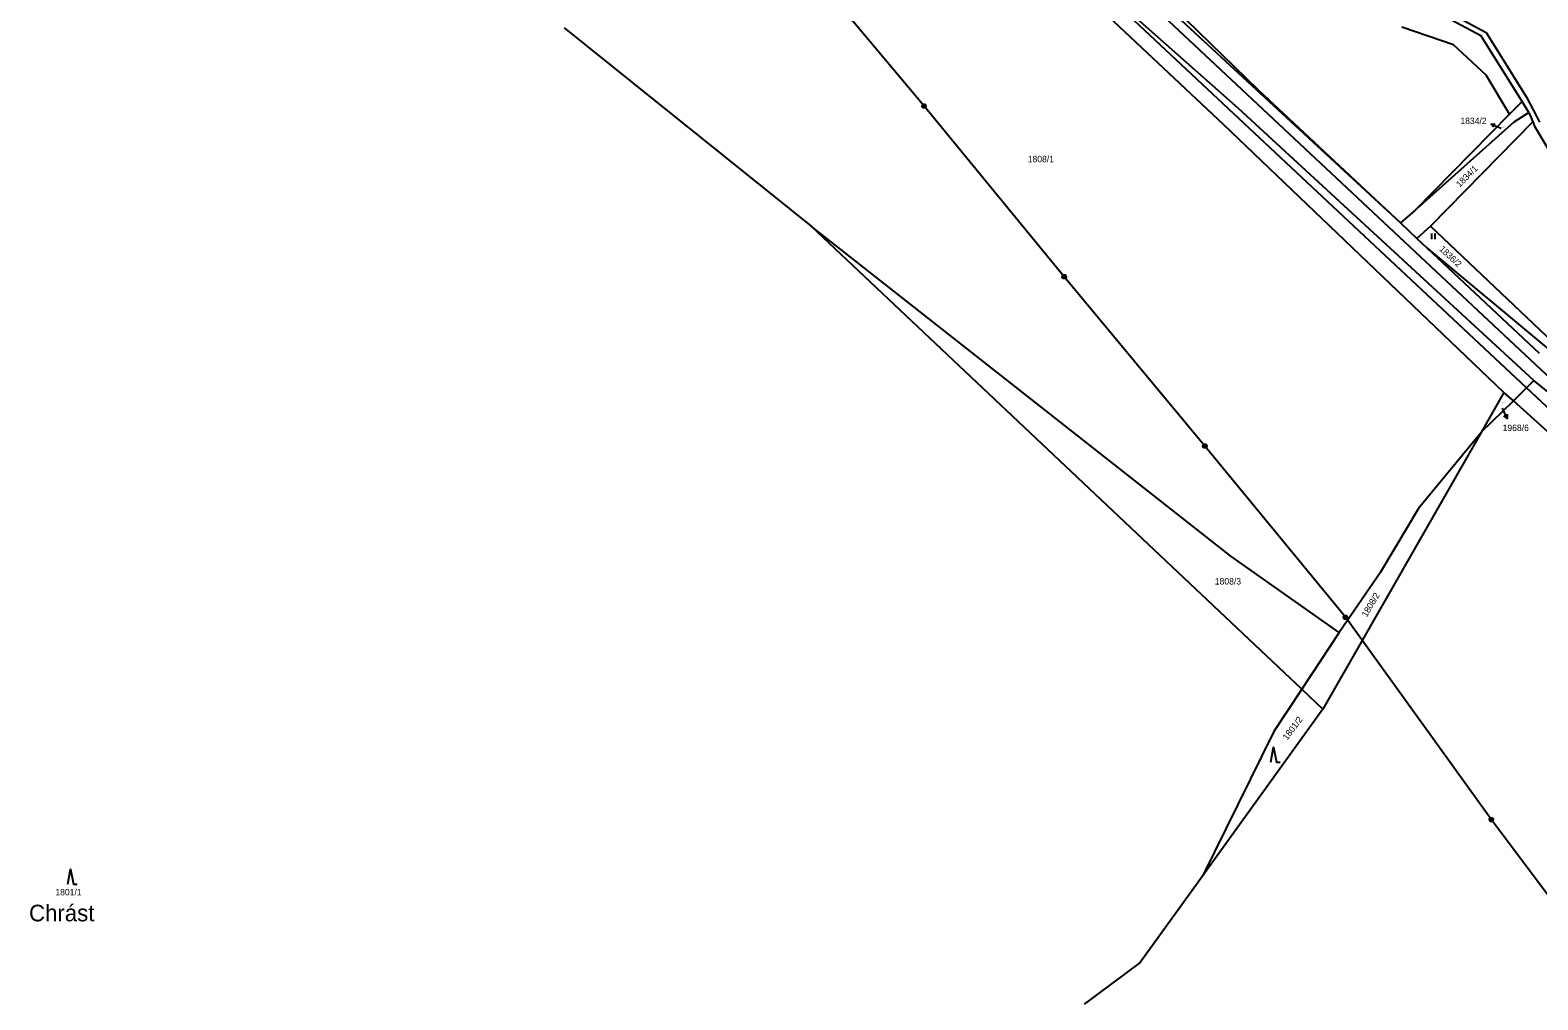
# Model space of a CAD drawing. Extents: x -609861 to -605046, y -1120287 to -1116307.
# Drawn here: x -608840.9 to -608441.3, y -1117503.3 to -1117246.3 of the extents above; entities that cross this region are included whole.
import ezdxf

# ---------------------------------------------------------------- set-up
doc = ezdxf.new("R2010")
doc.units = 0
for name, color, linetype in [('Vrstva 1', 7, 'Continuous'), ('Vrstva 2', 7, 'Continuous'), ('Vrstva 3', 7, 'Continuous'), ('Vrstva 4', 7, 'Continuous'), ('Vrstva 6', 7, 'Continuous'), ('Vrstva 7', 7, 'Continuous')]:
    doc.layers.add(name, color=color, linetype=linetype)

msp = doc.modelspace()

# ---------------------------------------------------------------- linework, layer by layer
at = {"layer": 'Vrstva 1'}
for p, q in [((-608590.8, -1117188.81), (-608515.44, -1117262.08)), ((-608524.53, -1117271.35), (-608600.24, -1117200.31)), ((-608574.9, -1117207.53), (-608477.78, -1117297.38)), ((-608520.72, -1117267.06), (-608572.58, -1117221.03)), ((-608500.17, -1117224.27), (-608456.42, -1117247.71)), ((-608499.28, -1117223.01), (-608455.01, -1117246.94)), ((-608699.42, -1117245.66), (-608633.95, -1117298.24)), ((-608463.71, -1117250.21), (-608477.37, -1117245.47)), ((-608445.51, -1117265.21), (-608456.42, -1117247.71)), ((-608455.01, -1117246.94), (-608444.36, -1117264.04)), ((-608455, -1117258.27), (-608463.71, -1117250.21)), ((-608448.84, -1117268.6), (-608455, -1117258.27)), ((-608515.44, -1117262.08), (-608477.78, -1117297.38)), ((-608444.36, -1117264.04), (-608441.55, -1117269.43)), ((-608442.38, -1117339.17), (-608520.72, -1117267.06)), ((-608448.84, -1117268.6), (-608473.99, -1117294.18)), ((-608445.51, -1117265.21), (-608448.84, -1117268.6)), ((-608447.65, -1117270.6), (-608443.72, -1117268.08)), ((-608443.72, -1117268.08), (-608445.51, -1117265.21)), ((-608443.72, -1117268.08), (-608442.7, -1117270.6)), ((-608450.31, -1117342.29), (-608524.53, -1117271.35)), ((-608473.99, -1117294.18), (-608447.65, -1117270.6)), ((-608442.7, -1117270.6), (-608469.83, -1117298.22)), ((-608442.7, -1117270.6), (-608442.25, -1117271.71)), ((-608442.25, -1117271.71), (-608437.03, -1117280.5)), ((-608441.55, -1117269.43), (-608440.91, -1117270.69)), ((-608473.99, -1117294.18), (-608477.78, -1117297.38)), ((-608522.68, -1117385.71), (-608633.95, -1117298.24)), ((-608633.95, -1117298.24), (-608503.88, -1117420.91)), ((-608477.78, -1117297.38), (-608473.41, -1117301.48)), ((-608469.83, -1117298.22), (-608473.41, -1117301.48)), ((-608417.92, -1117347.44), (-608469.83, -1117298.22)), ((-608473.41, -1117301.48), (-608470.76, -1117303.97)), ((-608470.76, -1117303.97), (-608438.52, -1117330.83)), ((-608470.76, -1117303.97), (-608440.95, -1117331.91)), ((-608442.38, -1117339.17), (-608444.34, -1117341.12)), ((-608406.86, -1117367.8), (-608442.38, -1117339.17)), ((-608450.31, -1117342.29), (-608456.3, -1117352.77)), ((-608456.3, -1117352.77), (-608447.8, -1117344.56)), ((-608447.8, -1117344.56), (-608450.31, -1117342.29)), ((-608444.34, -1117341.12), (-608447.8, -1117344.56)), ((-608385.67, -1117400.76), (-608447.8, -1117344.56)), ((-608456.3, -1117352.77), (-608498.29, -1117426.19)), ((-608472.65, -1117372.52), (-608456.3, -1117352.77)), ((-608482.96, -1117389.85), (-608472.65, -1117372.52)), ((-608493.97, -1117405.92), (-608522.68, -1117385.71)), ((-608482.96, -1117389.85), (-608493.97, -1117405.92)), ((-608493.97, -1117405.92), (-608503.88, -1117420.91)), ((-608503.88, -1117420.91), (-608511.33, -1117432.18)), ((-608503.88, -1117420.91), (-608498.29, -1117426.19)), ((-608498.29, -1117426.19), (-608530.22, -1117470.48)), ((-608511.33, -1117432.18), (-608530.22, -1117470.48)), ((-608530.22, -1117470.48), (-608546.7, -1117493.34)), ((-608546.7, -1117493.34), (-608561.55, -1117504.41))]:
    msp.add_line(p, q, dxfattribs=at)
at = {"layer": 'Vrstva 3'}
for p, q in [((-608469.52, -1117300.21), (-608469.52, -1117301.71)), ((-608468.52, -1117301.71), (-608468.52, -1117300.21))]:
    msp.add_line(p, q, dxfattribs=at)
for points in [[(-608512.12, -1117440.29), (-608511.37, -1117436.29), (-608510.62, -1117440.29), (-608509.62, -1117440.29)], [(-608830.98, -1117472.61), (-608830.23, -1117468.61), (-608829.48, -1117472.61), (-608828.48, -1117472.61)]]:
    msp.add_lwpolyline(points, dxfattribs=at)
at = {"layer": 'Vrstva 4'}
for p, q in [((-608686.51, -1117105.83), (-608406.86, -1117367.8)), ((-608444.34, -1117341.12), (-608572.58, -1117221.03)), ((-608150, -1117616.72), (-608444.34, -1117341.12))]:
    msp.add_line(p, q, dxfattribs=at)
at = {"layer": 'Vrstva 6'}
for p, q in [((-608604.03, -1117266.42), (-608643.31, -1117219.57)), ((-608566.89, -1117311.64), (-608604.03, -1117266.42)), ((-608529.6, -1117356.51), (-608566.89, -1117311.64)), ((-608492.36, -1117401.88), (-608529.6, -1117356.51)), ((-608453.65, -1117455.52), (-608492.36, -1117401.88)), ((-608418.77, -1117502.1), (-608453.65, -1117455.52))]:
    msp.add_line(p, q, dxfattribs=at)
for points in [[(-608604.18, -1117265.94), (-608603.87, -1117265.94), (-608603.62, -1117266.12), (-608603.52, -1117266.41), (-608603.62, -1117266.7), (-608603.87, -1117266.88), (-608604.18, -1117266.88), (-608604.43, -1117266.7), (-608604.53, -1117266.41), (-608604.43, -1117266.12), (-608604.18, -1117265.94), (-608604.15, -1117265.98), (-608603.91, -1117265.98), (-608603.75, -1117266.06), (-608604.31, -1117266.06), (-608604.39, -1117266.14), (-608603.67, -1117266.14), (-608603.67, -1117266.22), (-608604.39, -1117266.22), (-608604.43, -1117266.3), (-608603.63, -1117266.3), (-608603.59, -1117266.38), (-608604.47, -1117266.38), (-608604.47, -1117266.46), (-608603.59, -1117266.46), (-608603.62, -1117266.54), (-608604.43, -1117266.54), (-608604.42, -1117266.62), (-608603.61, -1117266.62), (-608603.66, -1117266.7), (-608604.38, -1117266.7), (-608604.3, -1117266.78), (-608603.74, -1117266.78), (-608603.85, -1117266.86), (-608604.19, -1117266.86)], [(-608567.04, -1117311.16), (-608566.73, -1117311.16), (-608566.48, -1117311.34), (-608566.38, -1117311.63), (-608566.48, -1117311.92), (-608566.73, -1117312.1), (-608567.04, -1117312.1), (-608567.29, -1117311.92), (-608567.39, -1117311.63), (-608567.29, -1117311.34), (-608567.04, -1117311.16), (-608567.01, -1117311.2), (-608566.77, -1117311.2), (-608566.61, -1117311.28), (-608567.17, -1117311.28), (-608567.25, -1117311.36), (-608566.53, -1117311.36), (-608566.53, -1117311.44), (-608567.25, -1117311.44), (-608567.29, -1117311.52), (-608566.49, -1117311.52), (-608566.45, -1117311.6), (-608567.33, -1117311.6), (-608567.33, -1117311.68), (-608566.45, -1117311.68), (-608566.48, -1117311.76), (-608567.29, -1117311.76), (-608567.28, -1117311.84), (-608566.47, -1117311.84), (-608566.52, -1117311.92), (-608567.24, -1117311.92), (-608567.16, -1117312), (-608566.6, -1117312), (-608566.71, -1117312.08), (-608567.05, -1117312.08)], [(-608529.75, -1117356.03), (-608529.44, -1117356.03), (-608529.19, -1117356.21), (-608529.09, -1117356.5), (-608529.19, -1117356.79), (-608529.44, -1117356.97), (-608529.75, -1117356.97), (-608530, -1117356.79), (-608530.1, -1117356.5), (-608530, -1117356.21), (-608529.75, -1117356.03), (-608529.72, -1117356.07), (-608529.48, -1117356.07), (-608529.32, -1117356.15), (-608529.88, -1117356.15), (-608529.96, -1117356.23), (-608529.24, -1117356.23), (-608529.24, -1117356.31), (-608529.96, -1117356.31), (-608530, -1117356.39), (-608529.2, -1117356.39), (-608529.16, -1117356.47), (-608530.04, -1117356.47), (-608530.04, -1117356.55), (-608529.16, -1117356.55), (-608529.19, -1117356.63), (-608530, -1117356.63), (-608529.99, -1117356.71), (-608529.18, -1117356.71), (-608529.23, -1117356.79), (-608529.95, -1117356.79), (-608529.87, -1117356.87), (-608529.31, -1117356.87), (-608529.42, -1117356.95), (-608529.76, -1117356.95)], [(-608492.51, -1117401.4), (-608492.2, -1117401.4), (-608491.95, -1117401.58), (-608491.85, -1117401.87), (-608491.95, -1117402.16), (-608492.2, -1117402.34), (-608492.51, -1117402.34), (-608492.76, -1117402.16), (-608492.86, -1117401.87), (-608492.76, -1117401.58), (-608492.51, -1117401.4), (-608492.48, -1117401.44), (-608492.24, -1117401.44), (-608492.08, -1117401.52), (-608492.64, -1117401.52), (-608492.72, -1117401.6), (-608492, -1117401.6), (-608492, -1117401.68), (-608492.72, -1117401.68), (-608492.76, -1117401.76), (-608491.96, -1117401.76), (-608491.92, -1117401.84), (-608492.8, -1117401.84), (-608492.8, -1117401.92), (-608491.92, -1117401.92), (-608491.95, -1117402), (-608492.76, -1117402), (-608492.75, -1117402.08), (-608491.94, -1117402.08), (-608491.99, -1117402.16), (-608492.71, -1117402.16), (-608492.63, -1117402.24), (-608492.07, -1117402.24), (-608492.18, -1117402.32), (-608492.52, -1117402.32)], [(-608453.8, -1117455.04), (-608453.49, -1117455.04), (-608453.24, -1117455.22), (-608453.14, -1117455.51), (-608453.24, -1117455.8), (-608453.49, -1117455.98), (-608453.8, -1117455.98), (-608454.05, -1117455.8), (-608454.15, -1117455.51), (-608454.05, -1117455.22), (-608453.8, -1117455.04), (-608453.77, -1117455.08), (-608453.53, -1117455.08), (-608453.37, -1117455.16), (-608453.93, -1117455.16), (-608454.01, -1117455.24), (-608453.29, -1117455.24), (-608453.29, -1117455.32), (-608454.01, -1117455.32), (-608454.05, -1117455.4), (-608453.25, -1117455.4), (-608453.21, -1117455.48), (-608454.09, -1117455.48), (-608454.09, -1117455.56), (-608453.21, -1117455.56), (-608453.24, -1117455.64), (-608454.05, -1117455.64), (-608454.04, -1117455.72), (-608453.23, -1117455.72), (-608453.28, -1117455.8), (-608454, -1117455.8), (-608453.92, -1117455.88), (-608453.36, -1117455.88), (-608453.47, -1117455.96), (-608453.81, -1117455.96)]]:
    msp.add_lwpolyline(points, dxfattribs=at)
at = {"layer": 'Vrstva 7'}
for p, q in [((-608453.7, -1117271.191), (-608451.05, -1117272.24)), ((-608449.506, -1117349.195), (-608450.67, -1117346.43))]:
    msp.add_line(p, q, dxfattribs=at)
for points in [[(-608452.991, -1117271.983), (-608453.7, -1117271.191), (-608452.642, -1117271.099)], [(-608449.433, -1117348.079), (-608449.506, -1117349.195), (-608450.355, -1117348.467)]]:
    msp.add_lwpolyline(points, dxfattribs=at)

# ---------------------------------------------------------------- texts
at = {"layer": 'Vrstva 2'}
for s, height, p in [('1834/2', 0.2, (-608451.004, -1117272.24)), ('1808/1', 1.7, (-608576.537, -1117281.3)), ('1968/6', 0.2, (-608450.694, -1117345.13)), ('1808/3', 1.7, (-608526.957, -1117393.2)), ('1801/1', 1.7, (-608834.267, -1117475.57))]:
    msp.add_text(s, height=height, dxfattribs=at).set_placement(p)
for s, rotation, p in [('1834/1', 44.97719, (-608462.012, -1117288.052)), ('1836/2', 316.78836, (-608467.594, -1117304.489)), ('1808/2', 59.41572, (-608486.69, -1117401.972)), ('1801/2', 53.11319, (-608507.754, -1117434.556))]:
    msp.add_text(s, height=1.7, rotation=rotation, dxfattribs=at).set_placement(p)
at = {"layer": 'Vrstva 7'}
for s, height, p in [('1834/2', 1.7, (-608461.862, -1117271.19)), ('1968/6', 1.7, (-608450.677, -1117352.52)), ('Chrást', 4.4, (-608841.244, -1117482.45))]:
    msp.add_text(s, height=height, dxfattribs=at).set_placement(p)

doc.saveas('drawing.dxf')
